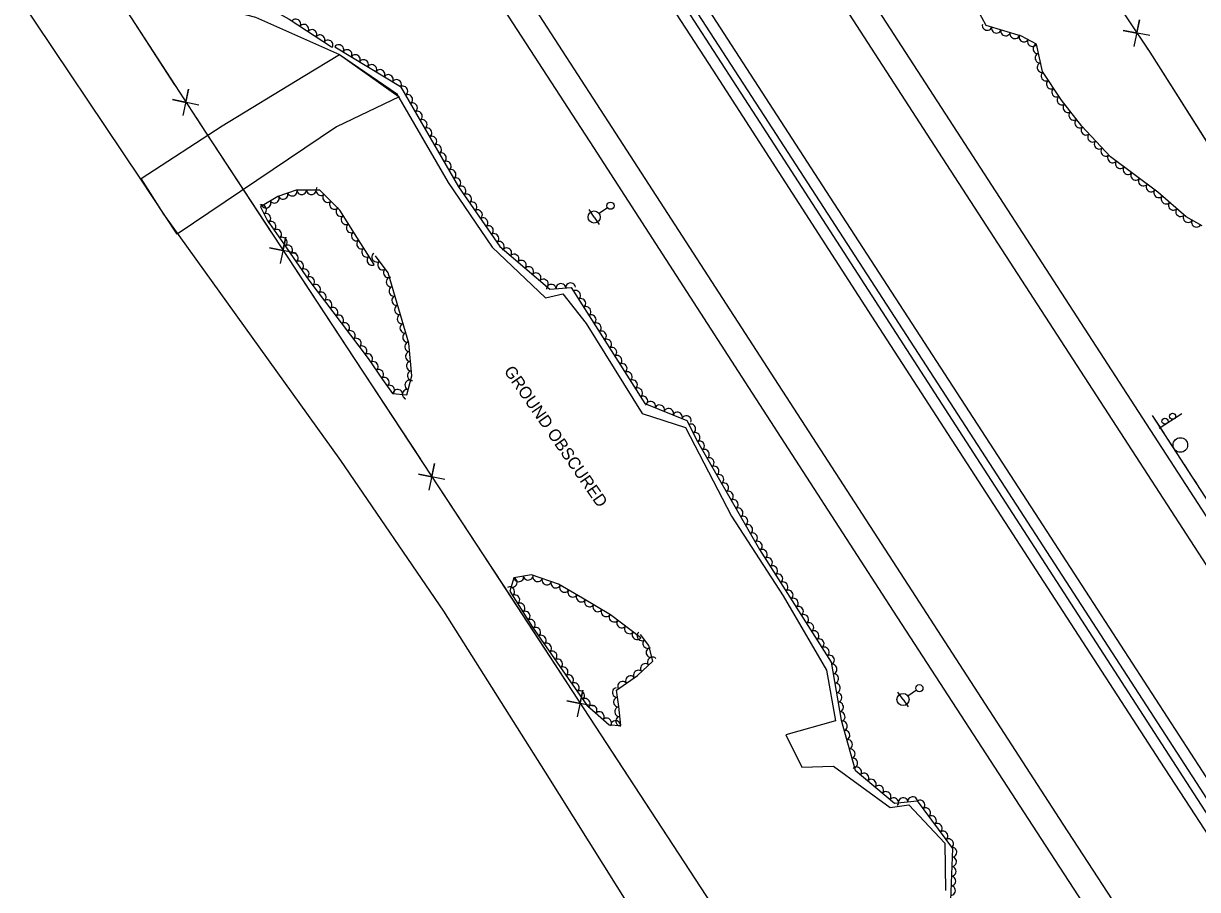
# Model space of a CAD drawing. Extents: x 1746719 to 1766531, y 631721 to 662391.
# Drawn here: x 1760154.9 to 1760642.5, y 640505.1 to 640864.7 of the extents above; entities that cross this region are included whole.
import ezdxf

# ---------------------------------------------------------------- set-up
doc = ezdxf.new("R2010")
doc.units = 0
for name, color, linetype in [('SURVEY - AERIAL SURVEY - Photo Control - Points - Elevations', 7, 'Continuous'), ('SURVEY - AERIAL SURVEY - Photo Control - Points - Locators', 7, 'Continuous'), ('SURVEY - AERIAL SURVEY - Photo Control - Points - Numbers', 7, 'Continuous'), ('SURVEY - AERIAL SURVEY - Photo Control with Text', 7, 'Continuous'), ('SURVEY - CENTERLINE - Existing Roads - Development', 7, 'Continuous'), ('SURVEY - CENTERLINE - Existing Roads Curve Text', 7, 'Continuous'), ('SURVEY - CONTROL - Grid', 7, 'Continuous')]:
    doc.layers.add(name, color=color, linetype=linetype)

msp = doc.modelspace()

# ---------------------------------------------------------------- linework, layer by layer
at = {"layer": 'SURVEY - AERIAL SURVEY - Photo Control - Points - Elevations'}
for points in [[(1761196.4, 639810.64), (1761146.73, 639886.96), (1761080.18, 639989.67), (1761013.55, 640093.35), (1760935.82, 640212.96), (1760859, 640331.61), (1760773.89, 640462.5), (1760694.04, 640586.22), (1760626.17, 640690.93), (1760539.47, 640824.63), (1760468.8, 640933.89), (1760453.88, 640957.11)], [(1761187.18, 639804.64), (1761137.51, 639880.97), (1761070.94, 639983.7), (1761004.31, 640087.38), (1760926.59, 640206.97), (1760849.77, 640325.63), (1760764.66, 640456.52), (1760684.8, 640580.25), (1760616.94, 640684.94), (1760530.24, 640818.65), (1760459.56, 640927.93), (1760444.62, 640951.16)], [(1761146.95, 639778.46), (1761097.25, 639854.83), (1761030.61, 639957.68), (1760963.99, 640061.33), (1760886.32, 640180.85), (1760809.51, 640299.5), (1760724.37, 640430.42), (1760644.5, 640554.18), (1760576.67, 640658.83), (1760489.95, 640792.56), (1760419.21, 640901.92), (1760404.24, 640925.21)], [(1760393.74, 640918.4), (1760441.13, 640845.23), (1760507.05, 640743.21), (1760565.58, 640652.81), (1760626.82, 640558.41), (1760688.54, 640463.7), (1760741.79, 640381.9), (1760794.12, 640301.16), (1760851.62, 640212.52), (1760925.86, 640097.46), (1760981.18, 640012.09), (1761038.81, 639922.4), (1761095.32, 639835.55), (1761136.33, 639771.93)], [(1760353.45, 640892.31), (1760400.83, 640819.16), (1760466.75, 640717.14), (1760525.3, 640626.7), (1760586.58, 640532.24), (1760648.32, 640437.5), (1760701.54, 640355.75), (1760753.85, 640275.04), (1760811.32, 640186.45), (1760885.27, 640071.83)], [(1760344.22, 640886.33), (1760391.59, 640813.18), (1760457.51, 640711.17), (1760516.07, 640620.72), (1760577.36, 640526.24), (1760639.11, 640431.5), (1760692.31, 640349.76), (1760744.62, 640269.06), (1760802.09, 640180.47), (1760875.81, 640066.21)]]:
    msp.add_lwpolyline(points, dxfattribs=at)
at = {"layer": 'SURVEY - AERIAL SURVEY - Photo Control - Points - Locators'}
for points in [[(1760152.9, 640984.79), (1760183.92, 640987.12), (1760212.27, 640942.31), (1760221.31, 640912.07), (1760212.6, 640906.3), (1760180.13, 640938.99), (1760153.3, 640933.88), (1760184.01, 640890.92), (1760225.29, 640874.04), (1760251.27, 640867.24), (1760286.21, 640851.81), (1760311, 640834.15), (1760284.86, 640821.73), (1760218.82, 640777.17), (1760203.73, 640800.08), (1760152.6, 640876.32)], [(1760203.82, 640800.26), (1760237.49, 640822.1), (1760271.09, 640842.6), (1760286.21, 640851.81), (1760309.87, 640835.54), (1760331.34, 640798.67), (1760349.54, 640771.86), (1760371.65, 640750.77), (1760378.91, 640752.39), (1760388.63, 640740.15), (1760411.81, 640702.78), (1760429.86, 640696.89), (1760449.01, 640660.13), (1760470.4, 640626.97), (1760488.39, 640596.15), (1760492.14, 640575.17), (1760471.56, 640569.3), (1760478.18, 640555.92), (1760491.28, 640556.3), (1760514.88, 640539.2), (1760522.58, 640540.19), (1760537.5, 640524.29), (1760537.82, 640504.74)], [(1760431.27, 640458.86), (1760371.65, 640553.87), (1760329.48, 640620.68), (1760286.72, 640683.24), (1760213.26, 640785.54), (1760203.82, 640800.26)]]:
    msp.add_lwpolyline(points, dxfattribs=at)
at = {"layer": 'SURVEY - AERIAL SURVEY - Photo Control - Points - Numbers'}
for points in [[(1761140.67, 639773.85), (1761073.58, 639878.26), (1760990.71, 640006.56), (1760880.55, 640175.62), (1760768.9, 640348.2), (1760647.19, 640535.4), (1760552.29, 640681.96), (1760459.27, 640825.92), (1760396.33, 640923.21)], [(1760398.55, 640924.9), (1760464.19, 640823.64), (1760557.54, 640679.57), (1760643.46, 640547.14), (1760726.42, 640418.31), (1760797.81, 640309.01), (1760889.3, 640167.21), (1760984.42, 640021.34), (1761065.75, 639894.94), (1761143.02, 639775.73)], [(1760925.05, 640236.95), (1760862.35, 640333.79), (1760777.25, 640464.67), (1760697.4, 640588.39), (1760623.82, 640701.9)], [(1760626, 640698.55), (1760623.82, 640701.9)], [(1760628.56, 640694.6), (1760626, 640698.55)], [(1760635.3, 640684.2), (1760630.3, 640691.92)], [(1760639.6, 640677.57), (1760637.04, 640681.51)], [(1760642.15, 640673.62), (1760639.6, 640677.57)]]:
    msp.add_lwpolyline(points, dxfattribs=at)
msp.add_arc((1760635.34, 640689.65), 3, 326.2185, 326.2045, dxfattribs=at)
at = {"layer": 'SURVEY - AERIAL SURVEY - Photo Control with Text'}
for points in [[(1760644.46, 640780.64), (1760637.69, 640784.42), (1760625.98, 640794.57), (1760606.35, 640809.3), (1760594.44, 640822.05), (1760586.01, 640832.89), (1760578.14, 640844.7), (1760575.65, 640856.08), (1760569.43, 640859.43), (1760554.75, 640863.83), (1760547.47, 640877.27), (1760540, 640904.04), (1760531.18, 640932.24), (1760528.29, 640936.28), (1760517.75, 640941.57), (1760507.68, 640946.6), (1760499, 640959.44), (1760489.11, 640983.73)], [(1760227.33, 640884.6), (1760233.11, 640884.41), (1760265.2, 640866.41), (1760282.81, 640854.98)], [(1760284.25, 640854.97), (1760311.56, 640838.47), (1760335.65, 640796.78), (1760352.77, 640772.04), (1760373.47, 640754.42), (1760382.32, 640755.08), (1760412.94, 640706.86), (1760430.42, 640699.83), (1760434.78, 640691.09), (1760460.59, 640646.32), (1760490.36, 640599.46), (1760494.48, 640575.36), (1760500.27, 640554.61), (1760516.63, 640540.97), (1760526.1, 640541.88), (1760540.69, 640522.18), (1760539.87, 640500.54)], [(1760300.6, 640764.6), (1760292.4, 640777.44), (1760286.25, 640787.12), (1760278.04, 640795.5), (1760268.23, 640795.5), (1760260.59, 640792.86), (1760253.38, 640788.57), (1760256.14, 640782.95), (1760262.96, 640773.28), (1760273.44, 640758.15), (1760286.91, 640740.34), (1760298.05, 640725.56), (1760304.06, 640716.87), (1760308.18, 640710.99), (1760314.14, 640710.53), (1760316.26, 640718.34), (1760315, 640731.88), (1760310.85, 640746.1), (1760306.36, 640761.08), (1760301.12, 640768.18)], [(1760411.25, 640609.58), (1760398.73, 640619.14), (1760387.08, 640626.05), (1760377.09, 640631.81), (1760365.93, 640635.69), (1760358.6, 640634.43), (1760356.88, 640628.91), (1760366.29, 640614.07), (1760379.85, 640594.49), (1760388.83, 640581.66), (1760398.08, 640573.5), (1760403.01, 640573.17), (1760402.1, 640581.04), (1760401.22, 640587.91), (1760409.87, 640593.89), (1760416.27, 640599.92), (1760414.64, 640606.38), (1760411.11, 640611.02)]]:
    msp.add_lwpolyline(points, dxfattribs=at)
for centre, major_axis in [((1760268.08, 640864.54), (1.68, -1.09)), ((1760271.43, 640862.37), (1.68, -1.09)), ((1760555.09, 640863.73), (-1.92, 0.57)), ((1760274.79, 640860.19), (1.68, -1.09)), ((1760278.14, 640858.01), (1.68, -1.09)), ((1760558.92, 640862.58), (-1.92, 0.57)), ((1760562.75, 640861.43), (-1.92, 0.57)), ((1760566.58, 640860.28), (-1.92, 0.57)), ((1760570.33, 640858.94), (-1.76, 0.95)), ((1760281.5, 640855.83), (1.68, -1.09)), ((1760285.96, 640853.94), (1.71, -1.03)), ((1760289.39, 640851.87), (1.71, -1.03)), ((1760573.85, 640857.05), (-1.76, 0.95)), ((1760576.07, 640854.16), (-0.43, 1.95)), ((1760292.81, 640849.8), (1.71, -1.03)), ((1760296.23, 640847.73), (1.71, -1.03)), ((1760576.92, 640850.26), (-0.43, 1.95)), ((1760299.66, 640845.66), (1.71, -1.03)), ((1760303.08, 640843.59), (1.71, -1.03)), ((1760577.78, 640846.35), (-0.43, 1.95)), ((1760579.42, 640842.78), (-1.11, 1.66)), ((1760306.5, 640841.52), (1.71, -1.03)), ((1760309.93, 640839.45), (1.71, -1.03)), ((1760581.64, 640839.45), (-1.11, 1.66)), ((1760312.61, 640836.66), (1, -1.73)), ((1760314.61, 640833.19), (1, -1.73)), ((1760583.86, 640836.12), (-1.11, 1.66)), ((1760316.61, 640829.73), (1, -1.73)), ((1760586.09, 640832.79), (-1.23, 1.58)), ((1760588.54, 640829.64), (-1.23, 1.58)), ((1760318.61, 640826.27), (1, -1.73)), ((1760320.61, 640822.8), (1, -1.73)), ((1760590.99, 640826.48), (-1.23, 1.58)), ((1760593.45, 640823.32), (-1.23, 1.58)), ((1760322.61, 640819.34), (1, -1.73)), ((1760596.07, 640820.3), (-1.37, 1.46)), ((1760324.62, 640815.88), (1, -1.73)), ((1760598.8, 640817.38), (-1.37, 1.46)), ((1760601.53, 640814.46), (-1.37, 1.46)), ((1760326.62, 640812.41), (1, -1.73)), ((1760328.62, 640808.95), (1, -1.73)), ((1760604.26, 640811.54), (-1.37, 1.46)), ((1760330.62, 640805.49), (1, -1.73)), ((1760607.1, 640808.74), (-1.6, 1.2)), ((1760610.3, 640806.34), (-1.6, 1.2)), ((1760332.62, 640802.02), (1, -1.73)), ((1760334.62, 640798.56), (1, -1.73)), ((1760613.5, 640803.93), (-1.6, 1.2)), ((1760616.7, 640801.53), (-1.6, 1.2)), ((1760266.57, 640794.93), (-1.89, -0.65)), ((1760270.48, 640795.5), (-2, 0)), ((1760274.48, 640795.5), (-2, 0)), ((1760278.35, 640795.19), (-1.4, 1.43)), ((1760336.76, 640795.18), (1.14, -1.64)), ((1760619.9, 640799.13), (-1.6, 1.2)), ((1760623.1, 640796.73), (-1.6, 1.2)), ((1760626.28, 640794.31), (-1.51, 1.31)), ((1760255.72, 640789.96), (-1.72, -1.02)), ((1760259.16, 640792.01), (-1.72, -1.02)), ((1760262.79, 640793.62), (-1.89, -0.65)), ((1760281.15, 640792.33), (-1.4, 1.43)), ((1760283.95, 640789.47), (-1.4, 1.43)), ((1760339.03, 640791.89), (1.14, -1.64)), ((1760341.31, 640788.6), (1.14, -1.64)), ((1760629.3, 640791.69), (-1.51, 1.31)), ((1760253.94, 640787.42), (0.88, -1.79)), ((1760255.7, 640783.83), (0.88, -1.79)), ((1760286.63, 640786.52), (-1.07, 1.69)), ((1760343.58, 640785.31), (1.14, -1.64)), ((1760632.33, 640789.07), (-1.51, 1.31)), ((1760635.35, 640786.45), (-1.51, 1.31)), ((1760257.87, 640780.49), (1.15, -1.63)), ((1760288.78, 640783.15), (-1.07, 1.69)), ((1760290.92, 640779.77), (-1.07, 1.69)), ((1760345.86, 640782.02), (1.14, -1.64)), ((1760348.14, 640778.73), (1.14, -1.64)), ((1760638.48, 640783.98), (-1.75, 0.97)), ((1760641.97, 640782.03), (-1.75, 0.97)), ((1760260.18, 640777.22), (1.15, -1.63)), ((1760262.49, 640773.95), (1.15, -1.63)), ((1760293.07, 640776.4), (-1.08, 1.69)), ((1760350.41, 640775.45), (1.14, -1.64)), ((1760264.77, 640770.67), (1.14, -1.64)), ((1760295.22, 640773.03), (-1.08, 1.69)), ((1760297.37, 640769.66), (-1.08, 1.69)), ((1760352.69, 640772.16), (1.14, -1.64)), ((1760355.71, 640769.54), (1.52, -1.3)), ((1760267.05, 640767.38), (1.14, -1.64)), ((1760269.32, 640764.09), (1.14, -1.64)), ((1760299.53, 640766.28), (-1.08, 1.69)), ((1760301.57, 640767.57), (-1.19, 1.61)), ((1760358.75, 640766.94), (1.52, -1.3)), ((1760361.8, 640764.35), (1.52, -1.3)), ((1760271.6, 640760.8), (1.14, -1.64)), ((1760303.95, 640764.35), (-1.19, 1.61)), ((1760306.32, 640761.14), (-1.19, 1.61)), ((1760364.84, 640761.76), (1.52, -1.3)), ((1760273.9, 640757.53), (1.21, -1.59)), ((1760276.32, 640754.34), (1.21, -1.59)), ((1760307.49, 640757.32), (-0.57, 1.92)), ((1760367.89, 640759.17), (1.52, -1.3)), ((1760370.94, 640756.57), (1.52, -1.3)), ((1760378.13, 640754.77), (1.99, 0.15)), ((1760382.12, 640755.06), (1.99, 0.15)), ((1760278.73, 640751.15), (1.21, -1.59)), ((1760308.64, 640753.48), (-0.57, 1.92)), ((1760374.14, 640754.47), (1.99, 0.15)), ((1760384.36, 640751.87), (1.07, -1.69)), ((1760281.14, 640747.96), (1.21, -1.59)), ((1760283.56, 640744.77), (1.21, -1.59)), ((1760309.79, 640749.65), (-0.57, 1.92)), ((1760310.93, 640745.82), (-0.56, 1.92)), ((1760386.5, 640748.49), (1.07, -1.69)), ((1760388.64, 640745.12), (1.07, -1.69)), ((1760285.97, 640741.58), (1.21, -1.59)), ((1760312.05, 640741.98), (-0.56, 1.92)), ((1760390.79, 640741.74), (1.07, -1.69)), ((1760288.38, 640738.39), (1.2, -1.6)), ((1760290.79, 640735.19), (1.2, -1.6)), ((1760313.17, 640738.14), (-0.56, 1.92)), ((1760392.93, 640738.36), (1.07, -1.69)), ((1760395.08, 640734.99), (1.07, -1.69)), ((1760293.2, 640732), (1.2, -1.6)), ((1760314.29, 640734.3), (-0.56, 1.92)), ((1760315.13, 640730.41), (-0.19, 1.99)), ((1760397.22, 640731.61), (1.07, -1.69)), ((1760295.6, 640728.81), (1.2, -1.6)), ((1760298.01, 640725.61), (1.2, -1.6)), ((1760315.5, 640726.42), (-0.19, 1.99)), ((1760399.36, 640728.23), (1.07, -1.69)), ((1760300.29, 640722.32), (1.14, -1.64)), ((1760315.87, 640722.44), (-0.19, 1.99)), ((1760401.51, 640724.86), (1.07, -1.69)), ((1760403.65, 640721.48), (1.07, -1.69)), ((1760302.56, 640719.03), (1.14, -1.64)), ((1760304.85, 640715.75), (1.15, -1.64)), ((1760316.24, 640718.46), (-0.19, 1.99)), ((1760405.8, 640718.1), (1.07, -1.69)), ((1760307.14, 640712.47), (1.15, -1.64)), ((1760310.36, 640710.82), (1.99, -0.15)), ((1760314.2, 640710.73), (0.52, 1.93)), ((1760315.24, 640714.59), (0.52, 1.93)), ((1760407.94, 640714.73), (1.07, -1.69)), ((1760410.08, 640711.35), (1.07, -1.69)), ((1760412.23, 640707.97), (1.07, -1.69)), ((1760415.42, 640705.86), (1.86, -0.75)), ((1760419.13, 640704.37), (1.86, -0.75)), ((1760422.85, 640702.87), (1.86, -0.75)), ((1760426.56, 640701.38), (1.86, -0.75)), ((1760430.27, 640699.89), (1.86, -0.75)), ((1760432.13, 640696.39), (0.89, -1.79)), ((1760433.92, 640692.82), (0.89, -1.79)), ((1760435.81, 640689.3), (1, -1.73)), ((1760437.81, 640685.83), (1, -1.73)), ((1760439.81, 640682.37), (1, -1.73)), ((1760441.81, 640678.9), (1, -1.73)), ((1760443.81, 640675.43), (1, -1.73)), ((1760445.81, 640671.97), (1, -1.73)), ((1760447.8, 640668.5), (1, -1.73)), ((1760449.8, 640665.04), (1, -1.73)), ((1760451.8, 640661.57), (1, -1.73)), ((1760453.8, 640658.11), (1, -1.73)), ((1760455.8, 640654.64), (1, -1.73)), ((1760457.79, 640651.18), (1, -1.73)), ((1760459.79, 640647.71), (1, -1.73)), ((1760461.88, 640644.3), (1.07, -1.69)), ((1760464.02, 640640.92), (1.07, -1.69)), ((1760466.17, 640637.55), (1.07, -1.69)), ((1760360.65, 640634.78), (-1.97, -0.34)), ((1760364.59, 640635.46), (-1.97, -0.34)), ((1760368.43, 640634.82), (-1.89, 0.66)), ((1760468.31, 640634.17), (1.07, -1.69)), ((1760356.95, 640628.79), (1.07, -1.69)), ((1760358.03, 640632.6), (-0.6, -1.91)), ((1760372.21, 640633.5), (-1.89, 0.66)), ((1760375.98, 640632.19), (-1.89, 0.66)), ((1760379.54, 640630.39), (-1.73, 1)), ((1760470.46, 640630.8), (1.07, -1.69)), ((1760359.09, 640625.41), (1.07, -1.69)), ((1760383.01, 640628.4), (-1.73, 1)), ((1760386.48, 640626.4), (-1.73, 1)), ((1760389.92, 640624.37), (-1.72, 1.02)), ((1760472.6, 640627.42), (1.07, -1.69)), ((1760474.75, 640624.04), (1.07, -1.69)), ((1760361.24, 640622.04), (1.07, -1.69)), ((1760363.38, 640618.66), (1.07, -1.69)), ((1760393.36, 640622.33), (-1.72, 1.02)), ((1760396.8, 640620.29), (-1.72, 1.02)), ((1760476.89, 640620.67), (1.07, -1.69)), ((1760365.52, 640615.28), (1.07, -1.69)), ((1760400.13, 640618.08), (-1.59, 1.21)), ((1760403.3, 640615.65), (-1.59, 1.21)), ((1760479.04, 640617.29), (1.07, -1.69)), ((1760481.18, 640613.91), (1.07, -1.69)), ((1760367.75, 640611.96), (1.14, -1.64)), ((1760370.03, 640608.67), (1.14, -1.64)), ((1760406.48, 640613.22), (-1.59, 1.21)), ((1760409.66, 640610.79), (-1.59, 1.21)), ((1760411.61, 640610.35), (-1.21, 1.59)), ((1760483.32, 640610.54), (1.07, -1.69)), ((1760372.31, 640605.39), (1.14, -1.64)), ((1760414.04, 640607.17), (-1.21, 1.59)), ((1760415.37, 640603.46), (-0.49, 1.94)), ((1760485.47, 640607.16), (1.07, -1.69)), ((1760487.61, 640603.78), (1.07, -1.69)), ((1760374.58, 640602.1), (1.14, -1.64)), ((1760376.86, 640598.81), (1.14, -1.64)), ((1760416.02, 640599.68), (1.46, 1.37)), ((1760489.76, 640600.41), (1.07, -1.69)), ((1760379.14, 640595.52), (1.14, -1.64)), ((1760410.2, 640594.2), (1.46, 1.37)), ((1760413.11, 640596.94), (1.46, 1.37)), ((1760490.85, 640596.62), (0.34, -1.97)), ((1760381.43, 640592.24), (1.15, -1.64)), ((1760383.72, 640588.96), (1.15, -1.64)), ((1760403.66, 640589.59), (1.64, 1.14)), ((1760406.95, 640591.87), (1.64, 1.14)), ((1760491.52, 640592.68), (0.34, -1.97)), ((1760492.19, 640588.74), (0.34, -1.97)), ((1760386.01, 640585.68), (1.15, -1.64)), ((1760401.35, 640586.88), (-0.25, 1.98)), ((1760492.87, 640584.8), (0.34, -1.97)), ((1760388.3, 640582.41), (1.15, -1.64)), ((1760391.14, 640579.62), (1.5, -1.32)), ((1760401.86, 640582.91), (-0.25, 1.98)), ((1760493.54, 640580.85), (0.34, -1.97)), ((1760394.14, 640576.97), (1.5, -1.32)), ((1760397.14, 640574.33), (1.5, -1.32)), ((1760402.34, 640578.94), (-0.23, 1.99)), ((1760402.8, 640574.97), (-0.23, 1.99)), ((1760494.21, 640576.91), (0.34, -1.97)), ((1760400.83, 640573.31), (2, -0.13)), ((1760495.13, 640573.02), (0.54, -1.93)), ((1760496.2, 640569.17), (0.54, -1.93)), ((1760497.28, 640565.32), (0.54, -1.93)), ((1760498.35, 640561.46), (0.54, -1.93)), ((1760499.43, 640557.61), (0.54, -1.93)), ((1760500.95, 640554.04), (1.54, -1.28)), ((1760504.02, 640551.48), (1.54, -1.28)), ((1760507.09, 640548.92), (1.54, -1.28)), ((1760510.17, 640546.36), (1.54, -1.28)), ((1760513.24, 640543.8), (1.54, -1.28)), ((1760516.31, 640541.24), (1.54, -1.28)), ((1760520.2, 640541.31), (1.99, 0.19)), ((1760524.18, 640541.69), (1.99, 0.19)), ((1760527.33, 640540.21), (1.19, -1.61)), ((1760529.71, 640537), (1.19, -1.61)), ((1760532.1, 640533.79), (1.19, -1.61)), ((1760534.48, 640530.57), (1.19, -1.61)), ((1760536.86, 640527.36), (1.19, -1.61)), ((1760539.24, 640524.14), (1.19, -1.61)), ((1760540.63, 640520.62), (-0.08, -2)), ((1760540.48, 640516.63), (-0.08, -2)), ((1760540.33, 640512.63), (-0.08, -2)), ((1760540.18, 640508.63), (-0.08, -2)), ((1760540.02, 640504.63), (-0.08, -2))]:
    msp.add_ellipse(centre, major_axis=major_axis, ratio=0.940188, start_param=0, end_param=3.141593, dxfattribs=at)
at = {"layer": 'SURVEY - CENTERLINE - Existing Roads - Development'}
for p, q in [((1760391.93, 640784.31), (1760389.79, 640787.39)), ((1760397.48, 640788.15), (1760393.98, 640785.73)), ((1760391.93, 640784.31), (1760394.06, 640781.22)), ((1760520.17, 640583.96), (1760518.03, 640587.04)), ((1760525.72, 640587.8), (1760522.22, 640585.38)), ((1760520.17, 640583.96), (1760522.3, 640580.88))]:
    msp.add_line(p, q, dxfattribs=at)
for centre, radius in [((1760391.93, 640784.31), 2.5), ((1760398.71, 640789), 1.5), ((1760520.17, 640583.96), 2.5), ((1760526.95, 640588.66), 1.5)]:
    msp.add_circle(centre, radius, dxfattribs=at)
at = {"layer": 'SURVEY - CENTERLINE - Existing Roads Curve Text'}
for points in [[(1760523.13, 641003.67), (1760556.48, 640952.68), (1760587.17, 640905.73), (1760622.62, 640852.72), (1760686.01, 640752.79), (1760748.96, 640654.51), (1760789.73, 640592.99), (1760831.97, 640527.72), (1760882.49, 640450.37), (1760943.59, 640353.92), (1761014.04, 640244.82), (1761096.19, 640117.07), (1761186.71, 639977.91), (1761265.97, 639858.91)], [(1760129.49, 640975.7), (1760167.62, 640917.11), (1760198.1, 640869.33), (1760230.51, 640819.5)], [(1760190.53, 640881.2), (1760198.1, 640869.33), (1760217.68, 640839.22)], [(1760622.7, 640859.62), (1760611.66, 640861.73), (1760617.21, 640860.63), (1760618.31, 640866.18), (1760616.05, 640855.17)], [(1760621.4, 640854.54), (1760622.62, 640852.72), (1760646.3, 640815.39)], [(1760227.82, 640830.78), (1760216.81, 640833.04), (1760222.34, 640831.87), (1760223.52, 640837.4), (1760221.12, 640826.42)], [(1760226.46, 640825.72), (1760230.51, 640819.5)], [(1760230.51, 640819.5), (1760345.86, 640644.08), (1760445.35, 640491.78), (1760535.04, 640345.21), (1760603.13, 640244.58), (1760729.8, 640049.09), (1760817.02, 639915.61)], [(1760230.51, 640819.5), (1760257.98, 640777.73)], [(1760268.16, 640769.34), (1760257.13, 640771.55), (1760262.67, 640770.4), (1760263.82, 640775.94), (1760261.48, 640764.95)], [(1760266.82, 640764.27), (1760292.32, 640725.5)], [(1760292.32, 640725.5), (1760319.79, 640683.73)], [(1760329.97, 640675.34), (1760318.94, 640677.55), (1760324.48, 640676.4), (1760325.63, 640681.94), (1760323.28, 640670.95)], [(1760328.63, 640670.27), (1760345.86, 640644.08), (1760354.09, 640631.48)], [(1760354.09, 640631.48), (1760381.43, 640589.62)], [(1760391.59, 640581.2), (1760380.57, 640583.44), (1760386.11, 640582.28), (1760387.27, 640587.82), (1760384.89, 640576.83)], [(1760390.24, 640576.14), (1760415.61, 640537.29)], [(1760415.61, 640537.29), (1760442.96, 640495.43)]]:
    msp.add_lwpolyline(points, dxfattribs=at)
at = {"layer": 'SURVEY - CONTROL - Grid'}
msp.add_line((1760635.98, 640702.63), (1760626.58, 640696.54), dxfattribs=at)
for centre in [(1760628.96, 640699.54), (1760632.11, 640701.58)]:
    msp.add_circle(centre, 1.25, dxfattribs=at)

# ---------------------------------------------------------------- texts
at = {"layer": 'SURVEY - AERIAL SURVEY - Photo Control - Points - Locators'}
msp.add_text('GROUND OBSCURED', height=5, rotation=304.6804, dxfattribs=at).set_placement((1760354.22, 640720.37))

doc.saveas('drawing.dxf')
